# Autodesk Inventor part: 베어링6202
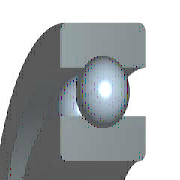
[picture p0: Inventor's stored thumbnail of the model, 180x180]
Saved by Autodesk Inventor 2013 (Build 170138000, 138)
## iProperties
IsCustomPart: 0
Company: 한국ATC센터
Created: 2014-12
Part Number: 베어링6202
Material: 강, 연강
Description: 깊은 그루브 볼 베어링
Document SubType Name: Modeling
Standard: KS B 2023
Designer: KYOUNG IL JANG
Standards Organization: KS
Language: ko-KR
Size Designation: 6202 - 15 x 35 x 11
Categories: <MemberInstance><Categories><Category DisplayName="샤프트 부품" InternalName="7f7aeb1f-a693-4053-b835-cee3144e0d98" Mnemonic="SHFT"><Category DisplayName="베어링" Inter
Density: 7.86 g/cm^3
Mass: 45.8725 g
Surface Area: 51.5584 cm^2
Volume: 5.83619 cm^3
Author: KYOUNG IL JANG
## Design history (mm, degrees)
sketch "스케치" dims "d0" = 5.2 (= -0.26 x WD + 0.26 x BD)
  geometry: L1 (2.9, 12.5)-(8.1, 12.5); L2 (5.5, 12.5)-(5.5, 9.9); L3 (5.5, 12.5)-(5.5, 15.1); L4 (3.568, 10.76)-(0, 10.76); L5 (0, 7.5)-(11, 7.5); L6 (3.568, 14.24)-(0, 14.24); L7 (0, 17.5)-(11, 17.5); L8 (11, 7.5)-(11, 10.76); L9 (7.432, 10.76)-(11, 10.76); L10 (7.432, 14.24)-(11, 14.24); L11 (11, 17.5)-(11, 14.24); L12 (-1.4, 0)-(8.4, 0) reference; L13 (0, -0.3)-(0, 5.3) reference
  constraints: 22 end point, 4 point on line, 2 collinear, 2 perpendicular, 2 symmetric about line, 1 midpoint, 1 parallel, 14 other
  dimensions: "d9" = 15 diameter of L5 L12 (= WD); "d11" = 35 diameter of L7 L12 (= BD); "d12" = 11 distance between parallel lines of L8 L13 (= KB); "d13" = 21.52 diameter of L9 L12 (= 0.326 x BD + 0.674 x WD)
revolve "본체" stored, may be unused: angle "d6" = 90 deg
revolve "볼" stored, may be unused: angle "d7" = 90 deg
pattern_circular "IDS_ARRAYBALL[SIMPL:T]" dims angle "d3" = 360 deg
body "Solid1"
fillet "모깎기1" dims "d1" = 0.6 (= KRS)
other parameters: "WD" = 15 [user parameter; used in 5 equation terms], "BD" = 35 [user parameter; used in 5 equation terms], "KB" = 11 [user parameter; used in 1 equation term], "KRS" = 0.6 [user parameter; used in 1 equation term], "d4" = 0, "d5" = 0, "d8" = 0, "d14" = 0, "d15" = 0, "BBA" = 0 [user parameter], "BC0" = 3750000 [user parameter], "BC" = 7800000 [user parameter], "BR" = 17.5 (= 0.5 x BD) [user parameter], "WR" = 7.5 (= 0.5 x WD) [user parameter]
